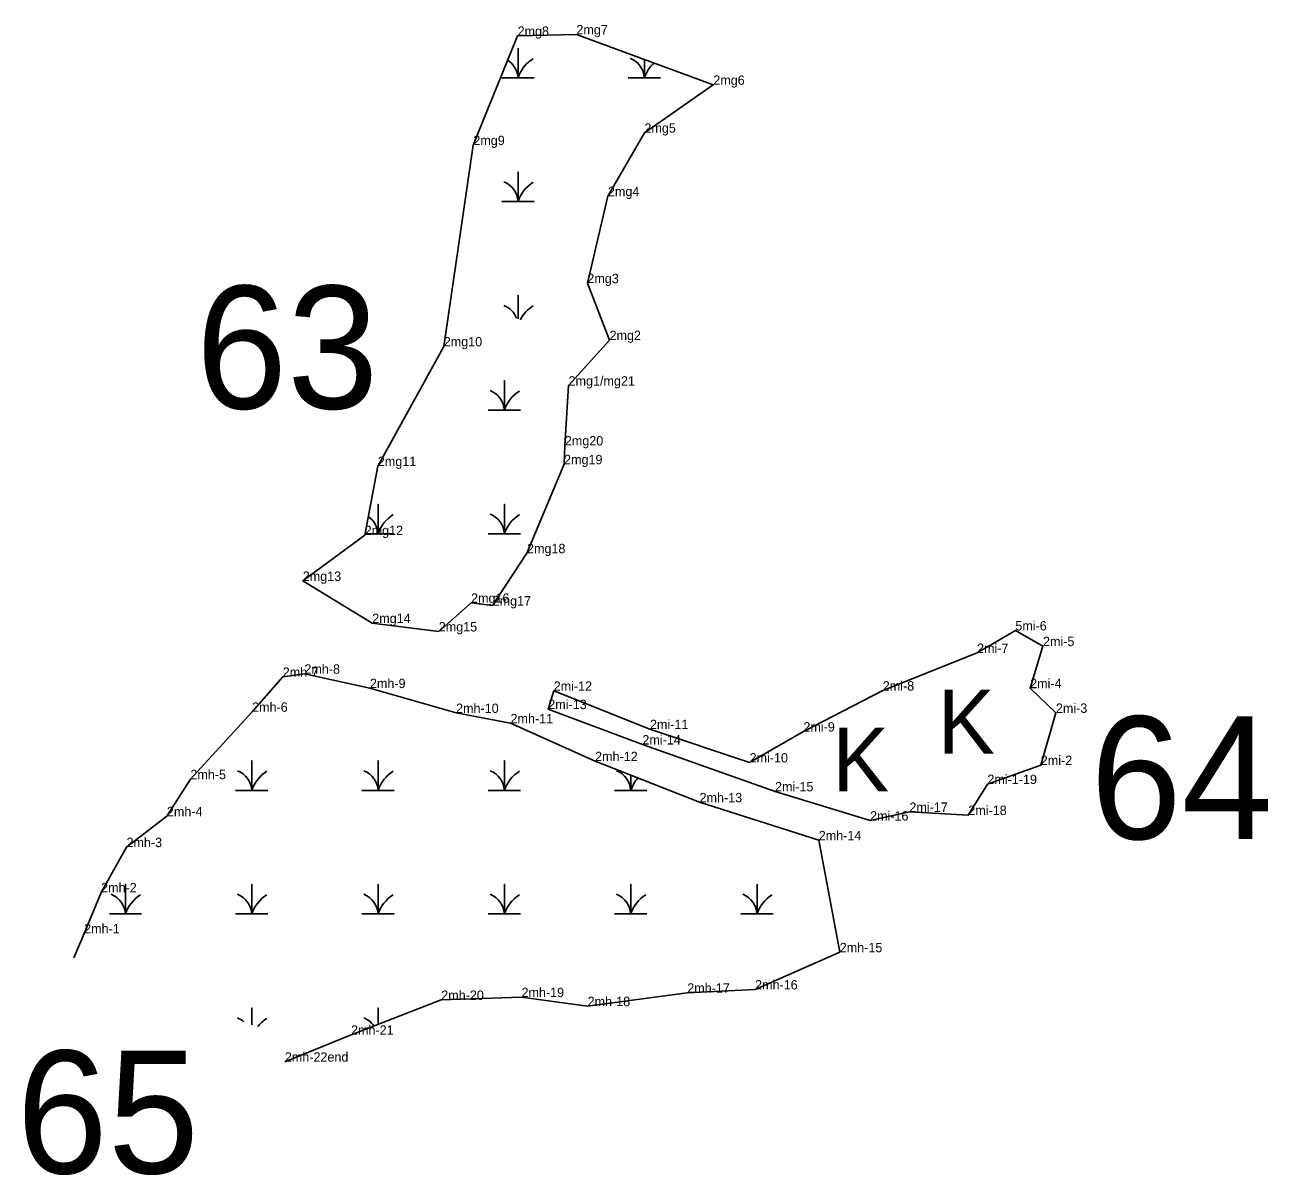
# Model space of a CAD drawing. Extents: x 2072529 to 2268796, y 436423 to 470406.
# Drawn here: x 2110069 to 2110730, y 452560 to 453172 of the extents above; entities that cross this region are included whole.
import ezdxf

# ---------------------------------------------------------------- set-up
doc = ezdxf.new("R2010")
doc.units = 0
for name, color, linetype in [('Default', 7, 'Continuous'), ('Exist Environmental Wetland Boundary Cogo Comment', 7, 'Continuous'), ('Exist Environmental Wetland Boundary Cogo Point CELL', 7, 'Continuous'), ('Old_Level_20', 7, 'Continuous')]:
    doc.layers.add(name, color=color, linetype=linetype)

msp = doc.modelspace()

# ---------------------------------------------------------------- linework, layer by layer
at = {"layer": 'Exist Environmental Wetland Boundary Cogo Point CELL'}
for points in [[(2110322.48, 453143.77), (2110331.08, 453143.77), (2110331.08, 453159.55), (2110331.08, 453143.77), (2110339.68, 453143.77)], [(2110389.73, 453143.77), (2110398.33, 453143.77), (2110398.33, 453153.6)], [(2110398.33, 453153.6), (2110398.33, 453143.77), (2110406.93, 453143.77)], [(2110322.48, 453077.97), (2110331.08, 453077.97), (2110331.08, 453093.75), (2110331.08, 453077.97), (2110339.68, 453077.97)], [(2110331.08, 453015.46), (2110331.08, 453027.95), (2110331.08, 453015.46)], [(2110315.23, 452966.81), (2110323.83, 452966.81), (2110323.83, 452982.59), (2110323.83, 452966.81), (2110332.43, 452966.81)], [(2110249.54, 452901.01), (2110256.58, 452901.01), (2110256.58, 452916.79), (2110256.58, 452901.01), (2110265.18, 452901.01)], [(2110315.23, 452901.01), (2110323.83, 452901.01), (2110323.83, 452916.79), (2110323.83, 452901.01), (2110332.43, 452901.01)], [(2110180.73, 452764.39), (2110189.33, 452764.39), (2110189.33, 452780.17), (2110189.33, 452764.39), (2110197.93, 452764.39)], [(2110247.98, 452764.39), (2110256.58, 452764.39), (2110256.58, 452780.17), (2110256.58, 452764.39), (2110265.18, 452764.39)], [(2110315.23, 452764.39), (2110323.83, 452764.39), (2110323.83, 452780.17), (2110323.83, 452764.39), (2110332.43, 452764.39)], [(2110382.48, 452764.39), (2110391.08, 452764.39), (2110391.08, 452772.49)], [(2110391.08, 452772.49), (2110391.08, 452764.39), (2110399.68, 452764.39)], [(2110113.48, 452698.59), (2110122.08, 452698.59), (2110122.08, 452714.37), (2110122.08, 452698.59), (2110130.68, 452698.59)], [(2110180.73, 452698.59), (2110189.33, 452698.59), (2110189.33, 452714.37), (2110189.33, 452698.59), (2110197.93, 452698.59)], [(2110247.98, 452698.59), (2110256.58, 452698.59), (2110256.58, 452714.37), (2110256.58, 452698.59), (2110265.18, 452698.59)], [(2110315.23, 452698.59), (2110323.83, 452698.59), (2110323.83, 452714.37), (2110323.83, 452698.59), (2110332.43, 452698.59)], [(2110382.48, 452698.59), (2110391.08, 452698.59), (2110391.08, 452714.37), (2110391.08, 452698.59), (2110399.68, 452698.59)], [(2110449.73, 452698.59), (2110458.33, 452698.59), (2110458.33, 452714.37), (2110458.33, 452698.59), (2110466.93, 452698.59)], [(2110189.33, 452639.59), (2110189.33, 452648.57), (2110189.33, 452639.59)], [(2110256.58, 452639.88), (2110256.58, 452648.57), (2110256.58, 452639.88)]]:
    msp.add_lwpolyline(points, dxfattribs=at)
for centre, radius, start, end in [((2110349.32, 453137.71), 19.22, 122.12745, 161.62219), ((2110386.06, 453142.88), 12.3, 4.14034, 67.53497), ((2110318.81, 453142.88), 12.3, 4.14034, 56.73112), ((2110416.57, 453137.71), 19.22, 133.16417, 161.62219), ((2110318.81, 453077.08), 12.3, 4.14034, 67.53497), ((2110349.32, 453071.91), 19.22, 122.12745, 161.62219), ((2110318.81, 453011.28), 12.3, 21.42276, 67.53497), ((2110349.32, 453006.11), 19.22, 122.12745, 152.41052), ((2110311.56, 452965.92), 12.3, 4.14034, 67.53497), ((2110342.07, 452960.75), 19.22, 122.12745, 161.62219), ((2110244.31, 452900.12), 12.3, 4.14034, 55.35145), ((2110274.82, 452894.95), 19.22, 122.12745, 161.62219), ((2110311.56, 452900.12), 12.3, 4.14034, 67.53497), ((2110342.07, 452894.95), 19.22, 122.12745, 161.62219), ((2110177.06, 452763.5), 12.3, 4.14034, 67.53497), ((2110207.57, 452758.33), 19.22, 122.12745, 161.62219), ((2110244.31, 452763.5), 12.3, 4.14034, 67.53497), ((2110274.82, 452758.33), 19.22, 122.12745, 161.62219), ((2110311.56, 452763.5), 12.3, 4.14034, 67.53497), ((2110342.07, 452758.33), 19.22, 122.12745, 161.62219), ((2110378.81, 452763.5), 12.3, 4.14034, 67.53497), ((2110409.32, 452758.33), 19.22, 138.7522, 161.62219), ((2110109.81, 452697.7), 12.3, 4.14034, 67.53497), ((2110140.32, 452692.53), 19.22, 122.12745, 161.62219), ((2110177.06, 452697.7), 12.3, 4.14034, 67.53497), ((2110207.57, 452692.53), 19.22, 122.12745, 161.62219), ((2110244.31, 452697.7), 12.3, 4.14034, 67.53497), ((2110274.82, 452692.53), 19.22, 122.12745, 161.62219), ((2110311.56, 452697.7), 12.3, 4.14034, 67.53497), ((2110342.07, 452692.53), 19.22, 122.12745, 161.62219), ((2110378.81, 452697.7), 12.3, 4.14034, 67.53497), ((2110409.32, 452692.53), 19.22, 122.12745, 161.62219), ((2110446.06, 452697.7), 12.3, 4.14034, 67.53497), ((2110476.57, 452692.53), 19.22, 122.12745, 161.62219), ((2110177.06, 452631.9), 12.3, 48.89427, 67.53497), ((2110207.57, 452626.73), 19.22, 122.12745, 142.38962), ((2110244.31, 452631.9), 12.3, 35.36832, 67.53497), ((2110274.82, 452626.73), 19.22, 122.12745, 122.53579)]:
    msp.add_arc(centre, radius, start, end, dxfattribs=at)
at = {"layer": 'Old_Level_20'}
for p, q in [((2110362.13, 453166.93), (2110362.13, 453166.93)), ((2110330.83, 453166.17), (2110330.83, 453166.17)), ((2110435.03, 453140.09), (2110435.03, 453140.09)), ((2110398.35, 453114.57), (2110398.35, 453114.57)), ((2110307.26, 453107.99), (2110307.26, 453107.99)), ((2110378.94, 453080.76), (2110378.94, 453080.76)), ((2110367.96, 453034.48), (2110367.96, 453034.48)), ((2110379.78, 453004.2), (2110379.78, 453004.2)), ((2110291.52, 453000.83), (2110291.52, 453000.83)), ((2110357.97, 452979.93), (2110357.97, 452979.93)), ((2110355.99, 452948.06), (2110355.99, 452948.06)), ((2110256.43, 452937.09), (2110256.43, 452937.09)), ((2110355.56, 452938.06), (2110355.56, 452938.06)), ((2110249.41, 452900.34), (2110249.41, 452900.34)), ((2110335.83, 452890.69), (2110335.83, 452890.69)), ((2110216.46, 452875.95), (2110216.46, 452875.95)), ((2110306.05, 452864.27), (2110306.05, 452864.27)), ((2110317.55, 452862.82), (2110317.55, 452862.82)), ((2110253.45, 452853.52), (2110253.45, 452853.52)), ((2110595.82, 452849.54), (2110595.82, 452849.54)), ((2110288.85, 452849.02), (2110288.85, 452849.02)), ((2110575.42, 452837.6), (2110575.42, 452837.6)), ((2110610.54, 452841.22), (2110610.54, 452841.22)), ((2110205.79, 452824.88), (2110205.79, 452824.88)), ((2110217.33, 452826.52), (2110217.33, 452826.52)), ((2110252.22, 452818.87), (2110252.22, 452818.87)), ((2110350.04, 452817.43), (2110350.04, 452817.43)), ((2110525.23, 452817.53), (2110525.23, 452817.53)), ((2110603.7, 452818.83), (2110603.7, 452818.83)), ((2110189.48, 452806.24), (2110189.48, 452806.24)), ((2110298.07, 452805.62), (2110298.07, 452805.62)), ((2110347.17, 452807.66), (2110347.17, 452807.66)), ((2110617.4, 452805.67), (2110617.4, 452805.67)), ((2110327.07, 452800.12), (2110327.07, 452800.12)), ((2110401.3, 452797.02), (2110401.3, 452797.02)), ((2110482.98, 452795.72), (2110482.98, 452795.72)), ((2110397.26, 452788.83), (2110397.26, 452788.83)), ((2110372.1, 452779.97), (2110372.1, 452779.97)), ((2110454.32, 452779.26), (2110454.32, 452779.26)), ((2110609.36, 452777.9), (2110609.36, 452777.9)), ((2110156.63, 452770.36), (2110156.63, 452770.36)), ((2110467.87, 452763.88), (2110467.87, 452763.88)), ((2110580.92, 452767.8), (2110580.92, 452767.8)), ((2110427.7, 452758.06), (2110427.7, 452758.06)), ((2110144.14, 452750.64), (2110144.14, 452750.64)), ((2110539.42, 452752.96), (2110539.42, 452752.96)), ((2110570.78, 452751.28), (2110570.78, 452751.28)), ((2110518.47, 452748.32), (2110518.47, 452748.32)), ((2110491.15, 452737.85), (2110491.15, 452737.85)), ((2110122.6, 452734.18), (2110122.6, 452734.18)), ((2110109.1, 452710.12), (2110109.1, 452710.12)), ((2110100.07, 452688.29), (2110100.07, 452688.29)), ((2110502.33, 452678.22), (2110502.33, 452678.22)), ((2110457.27, 452658.4), (2110457.27, 452658.4)), ((2110290.18, 452652.85), (2110290.18, 452652.85)), ((2110332.91, 452654.32), (2110332.91, 452654.32)), ((2110421.15, 452656.7), (2110421.15, 452656.7)), ((2110368.1, 452649.52), (2110368.1, 452649.52)), ((2110242.15, 452634.31), (2110242.15, 452634.31)), ((2110206.92, 452619.95), (2110206.92, 452619.95))]:
    msp.add_line(p, q, dxfattribs=at)
for points in [[(2110357.97, 452979.93), (2110379.78, 453004.2), (2110367.96, 453034.48), (2110378.94, 453080.76), (2110398.35, 453114.57), (2110435.03, 453140.09), (2110362.13, 453166.93), (2110330.83, 453166.17), (2110307.26, 453107.99), (2110291.52, 453000.83), (2110256.43, 452937.09), (2110249.41, 452900.34), (2110216.46, 452875.95), (2110253.45, 452853.52), (2110288.85, 452849.02), (2110306.05, 452864.27), (2110317.55, 452862.82), (2110335.83, 452890.69), (2110355.56, 452938.06), (2110355.99, 452948.06)], [(2110580.92, 452767.8), (2110609.36, 452777.9), (2110617.4, 452805.67), (2110603.7, 452818.83), (2110610.54, 452841.22), (2110595.82, 452849.54), (2110575.42, 452837.6), (2110525.23, 452817.53), (2110482.98, 452795.72), (2110454.32, 452779.26), (2110401.3, 452797.02), (2110350.04, 452817.43), (2110347.17, 452807.66), (2110397.26, 452788.83), (2110467.87, 452763.88), (2110518.47, 452748.32), (2110539.42, 452752.96), (2110570.78, 452751.28)]]:
    msp.add_lwpolyline(points, close=True, dxfattribs=at)
for points in [[(2110094.66, 452675.22), (2110100.07, 452688.29), (2110109.1, 452710.12), (2110122.6, 452734.18), (2110144.14, 452750.64), (2110156.63, 452770.36), (2110189.48, 452806.24), (2110205.79, 452824.88), (2110217.33, 452826.52), (2110252.22, 452818.87), (2110298.07, 452805.62), (2110327.07, 452800.12), (2110372.1, 452779.97), (2110427.7, 452758.06), (2110491.15, 452737.85), (2110502.33, 452678.22)], [(2110502.33, 452678.22), (2110457.27, 452658.4), (2110421.15, 452656.7), (2110368.1, 452649.52), (2110332.91, 452654.32), (2110290.18, 452652.85), (2110242.15, 452634.31), (2110206.92, 452619.95)]]:
    msp.add_lwpolyline(points, dxfattribs=at)

# ---------------------------------------------------------------- texts
at = {"layer": 'Default'}
for s, p in [('63', (2110159.55, 452967.68)), ('64', (2110635.77, 452738.49)), ('65', (2110064.07, 452560.47))]:
    msp.add_text(s, height=65.34, dxfattribs=at).set_placement(p)
at = {"layer": 'Exist Environmental Wetland Boundary Cogo Comment'}
for s, p in [('2mg8', (2110330.83, 453166.17)), ('2mg7', (2110362.13, 453166.93)), ('2mg6', (2110435.03, 453140.09)), ('2mg5', (2110398.35, 453114.57)), ('2mg9', (2110307.26, 453107.99)), ('2mg4', (2110378.94, 453080.76)), ('2mg3', (2110367.96, 453034.48)), ('2mg2', (2110379.78, 453004.2)), ('2mg10', (2110291.52, 453000.83)), ('2mg1/mg21', (2110357.97, 452979.93)), ('2mg20', (2110355.99, 452948.06)), ('2mg11', (2110256.43, 452937.09)), ('2mg19', (2110355.56, 452938.06)), ('2mg12', (2110249.41, 452900.34)), ('2mg18', (2110335.83, 452890.69)), ('2mg13', (2110216.46, 452875.95)), ('2mg16', (2110306.05, 452864.27)), ('2mg17', (2110317.55, 452862.82)), ('2mg14', (2110253.45, 452853.52)), ('2mg15', (2110288.85, 452849.02)), ('5mi-6', (2110595.82, 452849.54)), ('2mi-7', (2110575.42, 452837.6)), ('2mi-5', (2110610.54, 452841.22)), ('2mh-7', (2110205.79, 452824.88)), ('2mh-8', (2110217.33, 452826.52)), ('2mh-9', (2110252.22, 452818.87)), ('2mi-12', (2110350.04, 452817.43)), ('2mi-8', (2110525.23, 452817.53)), ('2mi-4', (2110603.7, 452818.83)), ('2mh-6', (2110189.48, 452806.24)), ('2mh-10', (2110298.07, 452805.62)), ('2mi-13', (2110347.17, 452807.66)), ('2mi-3', (2110617.4, 452805.67)), ('2mh-11', (2110327.07, 452800.12)), ('2mi-11', (2110401.3, 452797.02)), ('2mi-9', (2110482.98, 452795.72)), ('2mi-14', (2110397.26, 452788.83)), ('2mh-12', (2110372.1, 452779.97)), ('2mi-10', (2110454.32, 452779.26)), ('2mi-2', (2110609.36, 452777.9)), ('2mh-5', (2110156.63, 452770.36)), ('2mi-1-19', (2110580.92, 452767.8)), ('2mh-13', (2110427.7, 452758.06)), ('2mi-15', (2110467.87, 452763.88)), ('2mi-17', (2110539.42, 452752.96)), ('2mi-18', (2110570.78, 452751.28)), ('2mh-4', (2110144.14, 452750.64)), ('2mi-16', (2110518.47, 452748.32)), ('2mh-3', (2110122.6, 452734.18)), ('2mh-14', (2110491.15, 452737.85)), ('2mh-2', (2110109.1, 452710.12)), ('2mh-1', (2110100.07, 452688.29)), ('2mh-15', (2110502.33, 452678.22)), ('2mh-20', (2110290.18, 452652.85)), ('2mh-19', (2110332.91, 452654.32)), ('2mh-17', (2110421.15, 452656.7)), ('2mh-16', (2110457.27, 452658.4)), ('2mh-18', (2110368.1, 452649.52)), ('2mh-21', (2110242.15, 452634.31)), ('2mh-22end', (2110206.92, 452619.95))]:
    msp.add_text(s, height=5, dxfattribs=at).set_placement(p)
at = {"layer": 'Exist Environmental Wetland Boundary Cogo Point CELL'}
for p in [(2110554.54, 452784.02), (2110498.33, 452763.87)]:
    msp.add_text('K', height=34, dxfattribs=at).set_placement(p)

doc.saveas('drawing.dxf')
